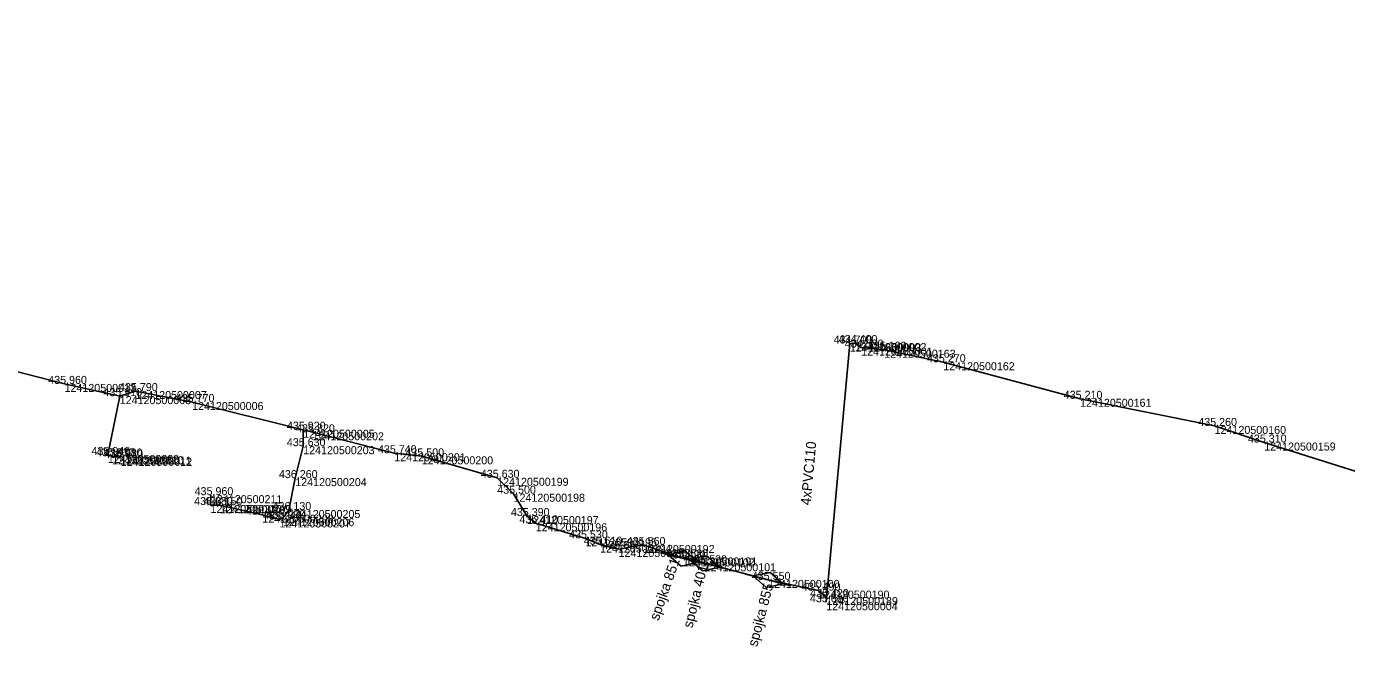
# Model space of a CAD drawing. Extents: x -637342 to -635997, y -1153616 to -1153154.
# Drawn here: x -636873.3 to -636675.3, y -1153411.5 to -1153318.4 of the extents above; entities that cross this region are included whole.
import ezdxf

# ---------------------------------------------------------------- set-up
doc = ezdxf.new("R2010")
doc.units = 0
for name, color, linetype in [('Vrstva 28', 7, 'Continuous'), ('Vrstva 35', 7, 'Continuous'), ('Vrstva 60', 7, 'Continuous'), ('Vrstva 61', 7, 'Continuous')]:
    doc.layers.add(name, color=color, linetype=linetype)

msp = doc.modelspace()

# ---------------------------------------------------------------- linework, layer by layer
at = {"layer": 'Vrstva 28'}
for p, q in [((-636860.43, -1153382.94), (-636859.17, -1153383.18)), ((-636778.21, -1153397.45), (-636771.43, -1153399.11)), ((-636777.08, -1153397.72), (-636774.54, -1153397.15)), ((-636775.1, -1153399.41), (-636777.08, -1153397.72)), ((-636774.98, -1153398.16), (-636768.2, -1153399.84)), ((-636774.54, -1153397.15), (-636772.56, -1153398.84)), ((-636773.85, -1153398.44), (-636771.31, -1153397.87)), ((-636771.87, -1153400.13), (-636773.85, -1153398.44)), ((-636771.31, -1153397.87), (-636769.33, -1153399.56)), ((-636772.56, -1153398.84), (-636775.1, -1153399.41)), ((-636769.33, -1153399.56), (-636771.87, -1153400.13)), ((-636765.45, -1153400.61), (-636758.69, -1153402.37)), ((-636764.32, -1153400.9), (-636761.78, -1153400.36)), ((-636761.78, -1153400.36), (-636759.82, -1153402.08)), ((-636762.36, -1153402.62), (-636764.32, -1153400.9)), ((-636759.82, -1153402.08), (-636762.36, -1153402.62))]:
    msp.add_line(p, q, dxfattribs=at)
for points in [[(-636859.31, -1153373.92), (-636867.59, -1153372.08), (-636889.87, -1153366.37), (-636896.7, -1153364.96), (-636901.09, -1153364.51), (-636913.66, -1153361.72), (-636934.13, -1153356.93), (-636945.13, -1153353.88), (-636947.14, -1153353.6), (-636955.43, -1153351.19), (-636972.02, -1153347.13), (-636986.79, -1153342.81), (-637001.85, -1153338.97), (-637018.07, -1153334.65), (-637042.74, -1153328.68), (-637062.52, -1153323.84), (-637073.89, -1153320.08), (-637082.06, -1153319.38), (-637087.31, -1153318.43)], [(-636748.12, -1153366.63), (-636749.04, -1153365.95), (-636749.8, -1153366.02), (-636753.36, -1153404.85)], [(-636671.19, -1153386.07), (-636687.67, -1153380.88), (-636695.11, -1153378.39), (-636715.29, -1153374.32), (-636735.8, -1153368.83), (-636744.67, -1153366.95), (-636748.12, -1153366.63)], [(-636831.79, -1153378.96), (-636848.46, -1153374.8), (-636856.97, -1153373.15), (-636859.31, -1153373.92), (-636861.1, -1153382.74), (-636860.43, -1153382.94), (-636859.25, -1153382.98)], [(-636753.36, -1153404.85), (-636753.32, -1153404.06), (-636754.58, -1153403.1), (-636762.07, -1153401.49), (-636771.59, -1153399), (-636774.42, -1153398.12), (-636774.82, -1153398.28), (-636780.82, -1153396.25), (-636784.5, -1153396.86), (-636787.28, -1153396.2), (-636789.47, -1153395.26), (-636796.92, -1153393), (-636798.2, -1153391.91), (-636800.25, -1153388.56), (-636802.71, -1153386.17), (-636814.02, -1153382.95), (-636818.14, -1153382.49), (-636830.4, -1153379.34), (-636831.79, -1153378.96), (-636831.8, -1153381.43), (-636832.99, -1153386.22), (-636833.94, -1153391.01), (-636834.84, -1153392.23), (-636835.35, -1153392.43), (-636837.93, -1153391.71), (-636844.28, -1153390.29), (-636845.7, -1153390.26), (-636845.63, -1153388.78)]]:
    msp.add_lwpolyline(points, dxfattribs=at)
at = {"layer": 'Vrstva 35'}
msp.add_lwpolyline([(-636753.36, -1153404.85), (-636749.8, -1153366.02), (-636749.04, -1153365.95)], dxfattribs=at)
at = {"layer": 'Vrstva 60'}
for p, q in [((-636749.8, -1153366.02), (-636749.8, -1153366.02)), ((-636749.04, -1153365.95), (-636749.04, -1153365.95)), ((-636748.12, -1153366.63), (-636748.12, -1153366.63)), ((-636744.67, -1153366.95), (-636744.67, -1153366.95)), ((-636735.8, -1153368.83), (-636735.8, -1153368.83)), ((-636867.59, -1153372.08), (-636867.59, -1153372.08)), ((-636859.31, -1153373.92), (-636859.31, -1153373.92)), ((-636856.97, -1153373.15), (-636856.97, -1153373.15)), ((-636848.46, -1153374.8), (-636848.46, -1153374.8)), ((-636715.29, -1153374.32), (-636715.29, -1153374.32)), ((-636831.79, -1153378.96), (-636831.79, -1153378.96)), ((-636695.11, -1153378.39), (-636695.11, -1153378.39)), ((-636830.4, -1153379.34), (-636830.4, -1153379.34)), ((-636687.67, -1153380.88), (-636687.67, -1153380.88)), ((-636861.1, -1153382.74), (-636861.1, -1153382.74)), ((-636831.8, -1153381.43), (-636831.8, -1153381.43)), ((-636818.14, -1153382.49), (-636818.14, -1153382.49)), ((-636860.43, -1153382.94), (-636860.43, -1153382.94)), ((-636859.25, -1153382.98), (-636859.25, -1153382.98)), ((-636859.17, -1153383.18), (-636859.17, -1153383.18)), ((-636814.02, -1153382.95), (-636814.02, -1153382.95)), ((-636832.99, -1153386.22), (-636832.99, -1153386.22)), ((-636802.71, -1153386.17), (-636802.71, -1153386.17)), ((-636845.63, -1153388.78), (-636845.63, -1153388.78)), ((-636800.25, -1153388.56), (-636800.25, -1153388.56)), ((-636845.7, -1153390.26), (-636845.7, -1153390.26)), ((-636844.28, -1153390.29), (-636844.28, -1153390.29)), ((-636837.93, -1153391.71), (-636837.93, -1153391.71)), ((-636835.35, -1153392.43), (-636835.35, -1153392.43)), ((-636834.84, -1153392.23), (-636834.84, -1153392.23)), ((-636833.94, -1153391.01), (-636833.94, -1153391.01)), ((-636798.2, -1153391.91), (-636798.2, -1153391.91)), ((-636796.92, -1153393), (-636796.92, -1153393)), ((-636789.47, -1153395.26), (-636789.47, -1153395.26)), ((-636787.28, -1153396.2), (-636787.28, -1153396.2)), ((-636780.82, -1153396.25), (-636780.82, -1153396.25)), ((-636784.5, -1153396.86), (-636784.5, -1153396.86)), ((-636774.82, -1153398.28), (-636774.82, -1153398.28)), ((-636774.42, -1153398.12), (-636774.42, -1153398.12)), ((-636771.59, -1153399), (-636771.59, -1153399)), ((-636762.07, -1153401.49), (-636762.07, -1153401.49)), ((-636754.58, -1153403.1), (-636754.58, -1153403.1)), ((-636753.32, -1153404.06), (-636753.32, -1153404.06)), ((-636753.36, -1153404.85), (-636753.36, -1153404.85))]:
    msp.add_line(p, q, dxfattribs=at)

# ---------------------------------------------------------------- texts
at = {"layer": 'Vrstva 28'}
for s, rotation, p in [('spojka 851', 70.4741, (-636778.52, -1153407.69)), ('spojka 401', 76.0843, (-636773.44, -1153408.81)), ('spojka 855', 75.3424, (-636763.72, -1153411.62))]:
    msp.add_text(s, height=1.5, rotation=rotation, dxfattribs=at).set_placement(p)
at = {"layer": 'Vrstva 35'}
msp.add_text('4xPVC110', height=1.5, rotation=84.7617, dxfattribs=at).set_placement((-636755.72, -1153390.34))
at = {"layer": 'Vrstva 60'}
for s, p in [('124120500003', (-636749.8, -1153367.22)), ('124120500002', (-636749.04, -1153367.15)), ('124120500001', (-636748.12, -1153367.83)), ('124120500163', (-636744.67, -1153368.15)), ('124120500162', (-636735.8, -1153370.03)), ('124120500013', (-636867.59, -1153373.28)), ('124120500008', (-636859.31, -1153375.12)), ('124120500007', (-636856.97, -1153374.35)), ('124120500006', (-636848.46, -1153376)), ('124120500161', (-636715.29, -1153375.52)), ('124120500005', (-636831.79, -1153380.16)), ('124120500160', (-636695.11, -1153379.59)), ('124120500202', (-636830.4, -1153380.54)), ('124120500159', (-636687.67, -1153382.08)), ('124120500009', (-636861.1, -1153383.94)), ('124120500010', (-636860.43, -1153384.14)), ('124120500203', (-636831.8, -1153382.63)), ('124120500201', (-636818.14, -1153383.69)), ('124120500200', (-636814.02, -1153384.15)), ('124120500011', (-636859.25, -1153384.18)), ('124120500012', (-636859.17, -1153384.38)), ('124120500204', (-636832.99, -1153387.42)), ('124120500199', (-636802.71, -1153387.37)), ('124120500211', (-636845.63, -1153389.98)), ('124120500198', (-636800.25, -1153389.76)), ('124120500210', (-636845.7, -1153391.46)), ('124120500209', (-636844.28, -1153391.49)), ('124120500208', (-636837.93, -1153392.91)), ('124120500207', (-636835.35, -1153393.63)), ('124120500206', (-636834.84, -1153393.43)), ('124120500205', (-636833.94, -1153392.21)), ('124120500197', (-636798.2, -1153393.11)), ('124120500196', (-636796.92, -1153394.2)), ('124120500195', (-636789.47, -1153396.46)), ('124120500194', (-636787.28, -1153397.4)), ('124120500192', (-636780.82, -1153397.45)), ('124120500193', (-636784.5, -1153398.06)), ('124120500102', (-636774.82, -1153399.48)), ('124120500191', (-636774.42, -1153399.32)), ('124120500101', (-636771.59, -1153400.2)), ('124120500100', (-636762.07, -1153402.69)), ('124120500190', (-636754.58, -1153404.3)), ('124120500189', (-636753.32, -1153405.26)), ('124120500004', (-636753.36, -1153406.05))]:
    msp.add_text(s, height=1.2, dxfattribs=at).set_placement(p)
at = {"layer": 'Vrstva 61'}
for s, p in [('434.700', (-636752.25, -1153366.02)), ('434.400', (-636751.49, -1153365.95)), ('434.580', (-636750.57, -1153366.63)), ('435.100', (-636747.12, -1153366.95)), ('435.270', (-636738.25, -1153368.83)), ('435.960', (-636870.04, -1153372.08)), ('435.910', (-636861.76, -1153373.92)), ('435.790', (-636859.42, -1153373.15)), ('435.770', (-636850.91, -1153374.8)), ('435.210', (-636717.74, -1153374.32)), ('435.920', (-636834.24, -1153378.96)), ('435.820', (-636832.85, -1153379.34)), ('435.260', (-636697.56, -1153378.39)), ('435.630', (-636834.25, -1153381.43)), ('435.310', (-636690.12, -1153380.88)), ('435.940', (-636863.55, -1153382.74)), ('435.830', (-636862.88, -1153382.94)), ('436.080', (-636861.7, -1153382.98)), ('435.930', (-636861.62, -1153383.18)), ('435.740', (-636820.59, -1153382.49)), ('435.500', (-636816.47, -1153382.95)), ('436.260', (-636835.44, -1153386.22)), ('435.630', (-636805.16, -1153386.17)), ('435.960', (-636848.08, -1153388.78)), ('435.500', (-636802.7, -1153388.56)), ('436.080', (-636848.15, -1153390.26)), ('436.150', (-636846.73, -1153390.29)), ('436.140', (-636840.38, -1153391.71)), ('436.130', (-636836.39, -1153391.01)), ('435.390', (-636800.65, -1153391.91)), ('435.940', (-636837.8, -1153392.43)), ('435.930', (-636837.29, -1153392.23)), ('435.410', (-636799.37, -1153393)), ('435.530', (-636791.92, -1153395.26)), ('435.610', (-636789.73, -1153396.2)), ('435.680', (-636786.95, -1153396.86)), ('435.560', (-636783.27, -1153396.25)), ('435.420', (-636777.27, -1153398.28)), ('435.520', (-636776.87, -1153398.12)), ('435.520', (-636774.04, -1153399)), ('435.550', (-636764.52, -1153401.49)), ('435.490', (-636757.03, -1153403.1)), ('435.620', (-636755.81, -1153404.85)), ('435.420', (-636755.77, -1153404.06))]:
    msp.add_text(s, height=1.2, dxfattribs=at).set_placement(p)

doc.saveas('drawing.dxf')
